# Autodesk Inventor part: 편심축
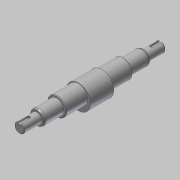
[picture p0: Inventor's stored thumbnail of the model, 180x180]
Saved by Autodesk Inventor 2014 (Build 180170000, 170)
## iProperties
Created: 2015-10
Part Number: 편심축
Document SubType Name: Modeling
Designer: mdu
Density: 7.86 g/cm^3
Material: 강철, 연강
Mass: 1255.63 g
Surface Area: 237.285 cm^2
Volume: 159.749 cm^3
Appearance: 강철
Author: mdu
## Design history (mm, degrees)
sketch "스케치6"
  geometry: L1 (-121, 0)-(121, 0); L2 (-121, 0)-(-121, 8.5); L3 (-121, 8.5)-(-91, 8.5); L4 (-91, 8.5)-(-91, 12.5); L5 (-91, 12.5)-(-57, 12.5); L6 (-57, 12.5)-(-57, 16); L7 (-57, 16)-(57, 16); L8 (57, 16)-(57, 12.5); L9 (57, 12.5)-(91, 12.5); L10 (91, 12.5)-(91, 8.5); L11 (91, 8.5)-(121, 8.5); L12 (121, 8.5)-(121, 0); 2 further points
  constraints: 24 end point, 7 parallel, 5 collinear, 2 perpendicular, 1 coincident, 1 horizontal, 1 midpoint, 1 vertical
  dimensions: "d39" = 242 distance of L1.start L1.end; "d41" = 30 distance of L2.end L3.end; "d42" = 34 distance of L4.end L5.end; "d43" = 17 diameter of L3 L1; "d44" = 25 diameter of L5 L1; "d45" = 32 diameter of L7 L1; "d65" = 114 distance of L6.end L7.end (derived)
revolve "회전2" sketch "스케치6" stored, may be unused: angle "d46" = 90 deg
node "작업 평면4"
sketch "스케치7"
  geometry: C1 r 20.75 at (0, -4); 1 further point
  constraints: 1 centre point, 1 vertical alignment
  dimensions: "d47" = 41.5 diameter of C1; "d48" = 4 distance of C1.centre point (0, 0)
extrude "돌출4" join sketch "스케치7" stored distance "d49" = 40; taper "d50" = 0 deg
chamfer "모따기1" distance "d11" = 1; stored, may be unused: second distance "d12" = 2, angle "d13" = 45 deg
node "작업 평면5"
sketch "스케치8"
  geometry: L1 (15, 7.5)-(15, -7.5) reference; L2 (15, 2.5)-(-0.5, 2.5); L3 (-0.5, 2.5)-(-0.5, -2.5); L4 (-0.5, -2.5)-(15, -2.5); L5 (15, -2.5)-(15, 2.5); 2 further points
  constraints: 8 end point, 2 parallel, 1 horizontal, 1 horizontal alignment, 1 midpoint, 1 perpendicular, 1 point on line, 1 vertical alignment, 2 other
  dimensions: "d51" = 18 dimension on L1; "d52" = 5 distance between parallel lines of L2 L4
extrude "돌출5" cut sketch "스케치8" distance "d53" = 3; taper "d54" = 0 deg
sketch "스케치9"
  geometry: L1 (56, 16)-(57, 15) reference; L2 (57, 15)-(57, 12.5) reference; L3 (57, 12.5)-(91, 12.5) reference; L4 (91, 12.5)-(91, 8.5) reference; L5 (91, 8.5)-(103, 8.5) reference; L6 (103, 8.5)-(103, 5.5) reference; L7 (103, 5.5)-(121, 5.5) reference; L8 (121, 5.5)-(121, -7.5) reference; L9 (121, -7.5)-(120, -8.5) reference; L10 (120, -8.5)-(91, -8.5) reference; L11 (91, -8.5)-(91, -12.5) reference; L12 (91, -12.5)-(57, -12.5) reference; L13 (57, -12.5)-(57, -15) reference; L14 (57, -15)-(56, -16) reference; L15 (56, -16)-(20, -16) reference; L16 (20, -16)-(20, -24.75) reference; L17 (20, -24.75)-(-20, -24.75) reference; L18 (-20, -24.75)-(-20, -16) reference; L19 (-20, -16)-(-56, -16) reference; L20 (-56, -16)-(-57, -15) reference; L21 (-57, -15)-(-57, -12.5) reference; L22 (-57, -12.5)-(-91, -12.5) reference; L23 (-91, -12.5)-(-91, -8.5) reference; L24 (-91, -8.5)-(-120, -8.5) reference; L25 (-120, -8.5)-(-121, -7.5) reference; L26 (-121, -7.5)-(-121, 5.5) reference; L27 (-121, 5.5)-(-103, 5.5) reference; L28 (-103, 5.5)-(-103, 8.5) reference; L29 (-103, 8.5)-(-91, 8.5) reference; L30 (-91, 8.5)-(-91, 12.5) reference; L31 (-91, 12.5)-(-57, 12.5) reference; L32 (-57, 12.5)-(-57, 15) reference; L33 (-57, 15)-(-56, 16) reference; L34 (-56, 16)-(-20, 16) reference; L35 (-20, 16)-(-20, 16.75) reference; L36 (-20, 16.75)-(20, 16.75) reference; L37 (20, 16.75)-(20, 16) reference; L38 (20, 16)-(56, 16) reference; L39 (0, 0)-(-121, 0); L40 (-91, 11.25)-(-88.835, 12.5); L41 (-88.835, 12.5)-(-91, 12.5); L42 (-91, 12.5)-(-91, 11.25)
  constraints: 8 end point, 3 point on line, 1 collinear, 1 parallel, 1 perpendicular
  dimensions: "d55" = 22.5 diameter of L40.start L39; "d56" = 30 deg angle of L40 L31
revolve "회전3" sketch "스케치9" stored, may be unused: angle "d57" = 90 deg
sketch "스케치10"
  geometry: L1 (56, 16)-(57, 15) reference; L2 (57, 15)-(57, 12.5) reference; L3 (57, 12.5)-(91, 12.5) reference; L4 (91, 12.5)-(91, 8.5) reference; L5 (91, 8.5)-(103, 8.5) reference; L6 (103, 8.5)-(103, 5.5) reference; L7 (103, 5.5)-(121, 5.5) reference; L8 (121, 5.5)-(121, -7.5) reference; L9 (121, -7.5)-(120, -8.5) reference; L10 (120, -8.5)-(91, -8.5) reference; L11 (91, -8.5)-(91, -12.5) reference; L12 (91, -12.5)-(57, -12.5) reference; L13 (57, -12.5)-(57, -15) reference; L14 (57, -15)-(56, -16) reference; L15 (56, -16)-(20, -16) reference; L16 (20, -16)-(20, -24.75) reference; L17 (20, -24.75)-(-20, -24.75) reference; L18 (-20, -24.75)-(-20, -16) reference; L19 (-20, -16)-(-56, -16) reference; L20 (-56, -16)-(-57, -15) reference; L21 (-57, -15)-(-57, -12.5) reference; L22 (-57, -12.5)-(-88.835, -12.5) reference; L23 (-88.835, -12.5)-(-91, -11.25) reference; L24 (-91, -11.25)-(-91, -8.5) reference; L25 (-91, -8.5)-(-120, -8.5) reference; L26 (-120, -8.5)-(-121, -7.5) reference; L27 (-121, -7.5)-(-121, 5.5) reference; L28 (-121, 5.5)-(-103, 5.5) reference; L29 (-103, 5.5)-(-103, 8.5) reference; L30 (-103, 8.5)-(-91, 8.5) reference; L31 (-91, 8.5)-(-91, 11.25) reference; L32 (-91, 11.25)-(-88.835, 12.5) reference; L33 (-88.835, 12.5)-(-57, 12.5) reference; L34 (-57, 12.5)-(-57, 15) reference; L35 (-57, 15)-(-56, 16) reference; L36 (-56, 16)-(-20, 16) reference; L37 (-20, 16)-(-20, 16.75) reference; L38 (-20, 16.75)-(20, 16.75) reference; L39 (20, 16.75)-(20, 16) reference; L40 (20, 16)-(56, 16) reference; L41 (0, 0)-(121, 0); L42 (91, 11.25)-(88.835, 12.5); L43 (88.835, 12.5)-(91, 12.5); L44 (91, 12.5)-(91, 11.25)
  constraints: 8 end point, 3 point on line, 1 collinear, 1 parallel, 1 perpendicular
  dimensions: "d58" = 22.5 diameter of L42.start L41; "d59" = 30 deg angle of L42 L43
revolve "회전4" sketch "스케치10" stored, may be unused: angle "d60" = 90 deg
fillet "모깎기1" dims "d61" = 4, "d62" = 0.5
fillet "모깎기2" dims "d63" = 4, "d64" = 0.5
node "솔리드1"
mirror "대칭2"
node "절단 모서리 투영1"
node "절단 모서리 투영2"
other parameters: "d30" = 35
